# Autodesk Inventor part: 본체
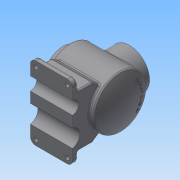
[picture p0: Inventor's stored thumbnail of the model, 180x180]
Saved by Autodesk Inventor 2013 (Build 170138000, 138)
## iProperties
Created: 2018-08
Part Number: 본체
Material: 일반
Document SubType Name: Modeling
Designer: Administrator
Density: 1 g/cm^3
Author: Administrator
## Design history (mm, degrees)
sketch "스케치1"
  geometry: L1 (0, 0)-(0, 38); L2 (0, 38)-(12, 38); L3 (12, 38)-(12, 50); L4 (12, 50)-(108.671, 50); L5 (0, 0)-(120, 0); A1 r 116 centre (4, 0) between (120, 0) and (108.671, 50)
  constraints: 10 end point, 3 parallel, 2 point on circle, 1 centre point, 1 perpendicular, 1 point on line, 1 vertical
  dimensions: "d0" = 12 distance between parallel lines of L3 L1; "d3" = 100 diameter of L4 L5; "d4" = 76 diameter of L2 L5; "d6" = 116 radius of A1; "d7" = 108 distance from line of L5.end L3
revolve "회전1" sketch "스케치1" stored, may be unused: angle "d8" = 90 deg
feature "쉘1" dims "d79" = 10
sketch "스케치2"
  geometry: C1 r 27 at (0, 0); 1 further point
  constraints: 1 centre point, 1 coincident
  dimensions: "d9" = 54 diameter of C1
extrude "돌출1" cut sketch "스케치2" distance "d10" = 50; taper "d11" = 0 deg
node "작업 평면1"
sketch "스케치3"
  geometry: L1 (0, 38)-(0, -38) reference; C1 r 38 at (-62, 0); 2 further points
  constraints: 1 centre point, 1 horizontal alignment, 1 midpoint
  dimensions: "d13" = 76 diameter of C1; "d14" = 62 distance from line of L1 C1.centre
extrude "돌출2" join sketch "스케치3" stored distance "d15" = 50; taper "d16" = 0 deg
sketch "스케치4"
  geometry: C1 r 38 at (0, 0) reference; C2 r 27 at (0, 0); 1 further point
  constraints: 1 centre point, 1 coincident
  dimensions: "d17" = 54 diameter of C2
extrude "돌출3" cut sketch "스케치4" distance "d18" = 50; taper "d19" = 0 deg
sketch "스케치5"
  geometry: 2 further points
  constraints: 1 vertical alignment
  dimensions: "d20" = 32.5 distance of point (0, 0) point (0, 32.5)
hole "구멍1" sketch "스케치5" at (0, 32.5) diameter "d21" = 3.242; stored, may be unused: countersink angle "d25" = 90 deg, drill point angle "d27" = 118 deg; dims "d22" = 8, "d23" = 4, "d24" = 2, "d26" = 10
sketch "스케치6"
  geometry: C1 r 27 at (0, 0) reference; 2 further points
  constraints: 1 vertical alignment
  dimensions: "d31" = 32.5 distance of C1.centre point (0, 32.5)
hole "구멍2" sketch "스케치6" at (0, 32.5) diameter "d32" = 3.242; stored, may be unused: countersink angle "d36" = 90 deg, drill point angle "d38" = 118 deg; dims "d33" = 8, "d34" = 4, "d35" = 2, "d37" = 10
node "작업 평면3"
sketch "스케치7"
  geometry: L1 (20, 70)-(100, 70); L2 (100, 70)-(100, -70); L3 (100, -70)-(20, -70); L4 (20, -70)-(20, 70); L5 (12, -50)-(12, 50) reference; 3 further points
  constraints: 8 end point, 2 midpoint, 2 parallel, 1 horizontal, 1 horizontal alignment, 1 perpendicular
  dimensions: "d44" = 80 distance of L2.end L3.end; "d46" = 140 distance of L1.end L2.end; "d47" = 8 distance between parallel lines of L4 L5
extrude "돌출4" join sketch "스케치7" distance "d48" = 10; taper "d49" = 0 deg
node "작업 평면4"
sketch "스케치8"
  geometry: L1 (65, -37.947)-(32.558, -37.947) reference; L2 (32.558, 37.947)-(65, 37.947) reference; L3 (65, 37.947)-(65, 26.926) reference; L4 (65, 26.926)-(29.58, 26.926) reference; L5 (29.58, -26.926)-(65, -26.926) reference; L6 (65, -26.926)-(65, -37.947) reference; L7 (-82, 70)-(-72, 70) reference; L8 (-72, 70)-(-72, -70) reference; L9 (-72, -70)-(-82, -70) reference; L10 (-82, -70)-(-82, 70) reference; L11 (-29.59, -40.304)-(-72, -70); L12 (-29.59, 40.304)-(-72, 70); A1 r 50 centre (0, 0) between (32.558, 37.947) and (32.558, -37.947) reference; A2 r 40 centre (0, 0) between (29.58, 26.926) and (29.58, -26.926) reference; 1 further point
  constraints: 4 end point, 2 point on circle
  dimensions: "d51" = 35 deg angle of L9 L11; "d52" = 35 deg angle of L7 L12
extrude "돌출5" join sketch "스케치8" stored distance "d53" = 80; taper "d54" = 0 deg
sketch "스케치9"
  geometry: L1 (29.696, 52.41)-(0, 10) reference; L2 (0, 0)-(0, 10) reference; L3 (140, 10)-(110.304, 52.41) reference; L4 (140, 0)-(140, 10) reference; L5 (140, 10)-(120, 10); L6 (120, 10)-(120, 38.563); L7 (0, 10)-(20, 10); L8 (20, 10)-(20, 38.563); 1 further point
  constraints: 8 end point, 4 perpendicular, 2 point on line
  dimensions: "d55" = 20 distance of L3.start L5.end; "d56" = 20 distance of L1.end L7.end
extrude "돌출6" cut sketch "스케치9" stored distance "d57" = 80; taper "d58" = 0 deg
sketch "스케치10"
  geometry: C1 r 17.5 at (47.5, -3.398); C2 r 12.5 at (97.5, -0.502); 1 further point
  constraints: 2 centre point
  dimensions: "d59" = 17.5 radius of C1; "d60" = 12.5 radius of C2; "d61" = 22.5 horizontal distance of C1.centre point (70, 82); "d62" = 27.5 horizontal distance of point (70, 82) C2.centre
extrude "돌출7" cut sketch "스케치10" stored distance "d63" = 80; taper "d64" = 0 deg
node "작업 평면5"
sketch "스케치11"
  geometry: C1 r 32.5 at (0, 0); 1 further point
  constraints: 1 centre point, 1 coincident, 1 other
  dimensions: "d66" = 32.5 radius of C1
feature "엠보싱1" sketch "스케치11" dims "d0" = 12, "d3" = 100, "d4" = 76, "d6" = 116, "d7" = 108, "d67" = 0.5, "d68" = 0
fillet "모깎기1" dims "d69" = 10
sketch "스케치12"
  geometry: A1 r 10 centre (10, 10) between (10, 20) and (0, 10) reference; A2 r 10 centre (70, 10) between (80, 10) and (70, 20) reference; A3 r 10 centre (70, -110) between (70, -120) and (80, -110) reference; A4 r 10 centre (10, -110) between (0, -110) and (10, -120) reference; 5 further points
  constraints: 4 coincident
hole "구멍3" sketch "스케치12" at (10, 10), (70, 10), (70, -110), (10, -110) diameter "d70" = 8; stored, may be unused: countersink angle "d74" = 90 deg, drill point angle "d76" = 118 deg; dims "d71" = 8, "d72" = 4, "d73" = 2, "d75" = 10
fillet "모깎기2" dims "d77" = 3
fillet "모깎기3" dims "d78" = 3
chamfer "모따기1" distance "d83" = 1; stored, may be unused: second distance "d84" = 2, angle "d85" = 45 deg
fillet "모깎기4" dims "d86" = 3
sketch "스케치15"
  geometry: C1 r 29 at (0, 0) reference; C2 r 27 at (0, 0); 1 further point
  constraints: 1 centre point, 1 coincident
  dimensions: "d87" = 54 diameter of C2
extrude "돌출8" join sketch "스케치15" distance "d88" = 22; taper "d89" = 0 deg
node "솔리드1"
pattern_circular "원형 패턴2" dims angle "d40" = 360 deg
pattern_circular "원형 패턴3" dims angle "d81" = 360 deg
node "절단 모서리 투영1"
other parameters: "d12" = 65, "d43" = -82, "d65" = 193
